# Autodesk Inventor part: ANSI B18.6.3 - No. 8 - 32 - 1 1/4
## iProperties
Comments: To add or edit properties for Autodesk Inventor files, use iProperties.
Created: 2005-01
Part Number: ANSI B18.6.3 - No. 8 - 32 - 1 1/4
Vendor: Autodesk Inc.
Document SubType Name: Modeling
Designer: John Blackburn
Material: Default
Description: Plain Hex Head Machine Screw
Standard: ANSI B18.6.3
Alert: To add or edit properties for Autodesk Inventor files, use iProperties.
Control State: 0
Master: False
Checked Out: False
Shininess: 64.0
Length Units: 11272
Angle Units: 11279
Time Units: 11290
Mass Units: 11286
Length Display Precision: 3
Angle Display Precision: 2
Compacted: True
EGR: 3
Classification: un/spsc 31161513
Density: 0.0
Volumn: 0.0
Area: 0.0
PropertySet Name: Model Information
Author: John Blackburn
Revision Number: 8
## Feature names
1. Body [Revolution]
2. Head [Extrusion]
3. Chamfer1 [Revolution]
4. Chamfer2
